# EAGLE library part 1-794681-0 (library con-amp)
Micro MATE-N-LOK Connectors grid 1.5mm Dual Row Through Hole Vertical Metal Through Hole Holddowns Source: ENG_CD_794681_E.pdf
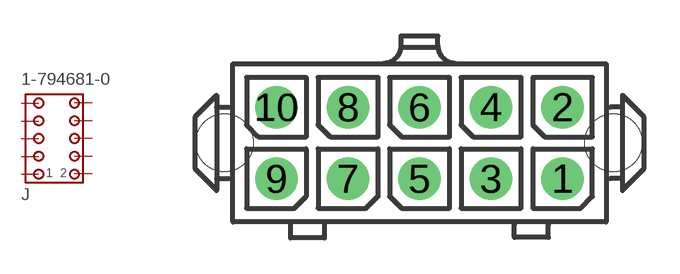
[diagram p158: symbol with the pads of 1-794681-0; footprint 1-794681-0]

Designator prefix J

## 1-794681-0 (MF: TYCO ELECTRONICS; MPN: 1-794681-0; OC_FARNELL: unknown; OC_NEWARK: 10H3809)  [1-794681-0]
1  1  pas
2  2  pas
3  3  pas
4  4  pas
5  5  pas
6  6  pas
7  7  pas
8  8  pas
9  9  pas
10  10  pas

## Footprint 1-794681-0 (pad centres in mm)
Micro MATE-N-LOK Connectors grid 1.5mm Dual Row Through Hole Vertical Metal Through Hole Holddowns Source: ENG_CD_794681_E.pdf
drill 1 pad 1.778 round: 1 6,-1.5; 2 6,1.5; 3 3,-1.5; 4 3,1.5; 5 0,-1.5; 6 0,1.5; 7 -3,-1.5; 8 -3,1.5; 9 -6,-1.5; 10 -6,1.5
hole 2.4 at 8.13,0
hole 2.4 at -8.17,0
